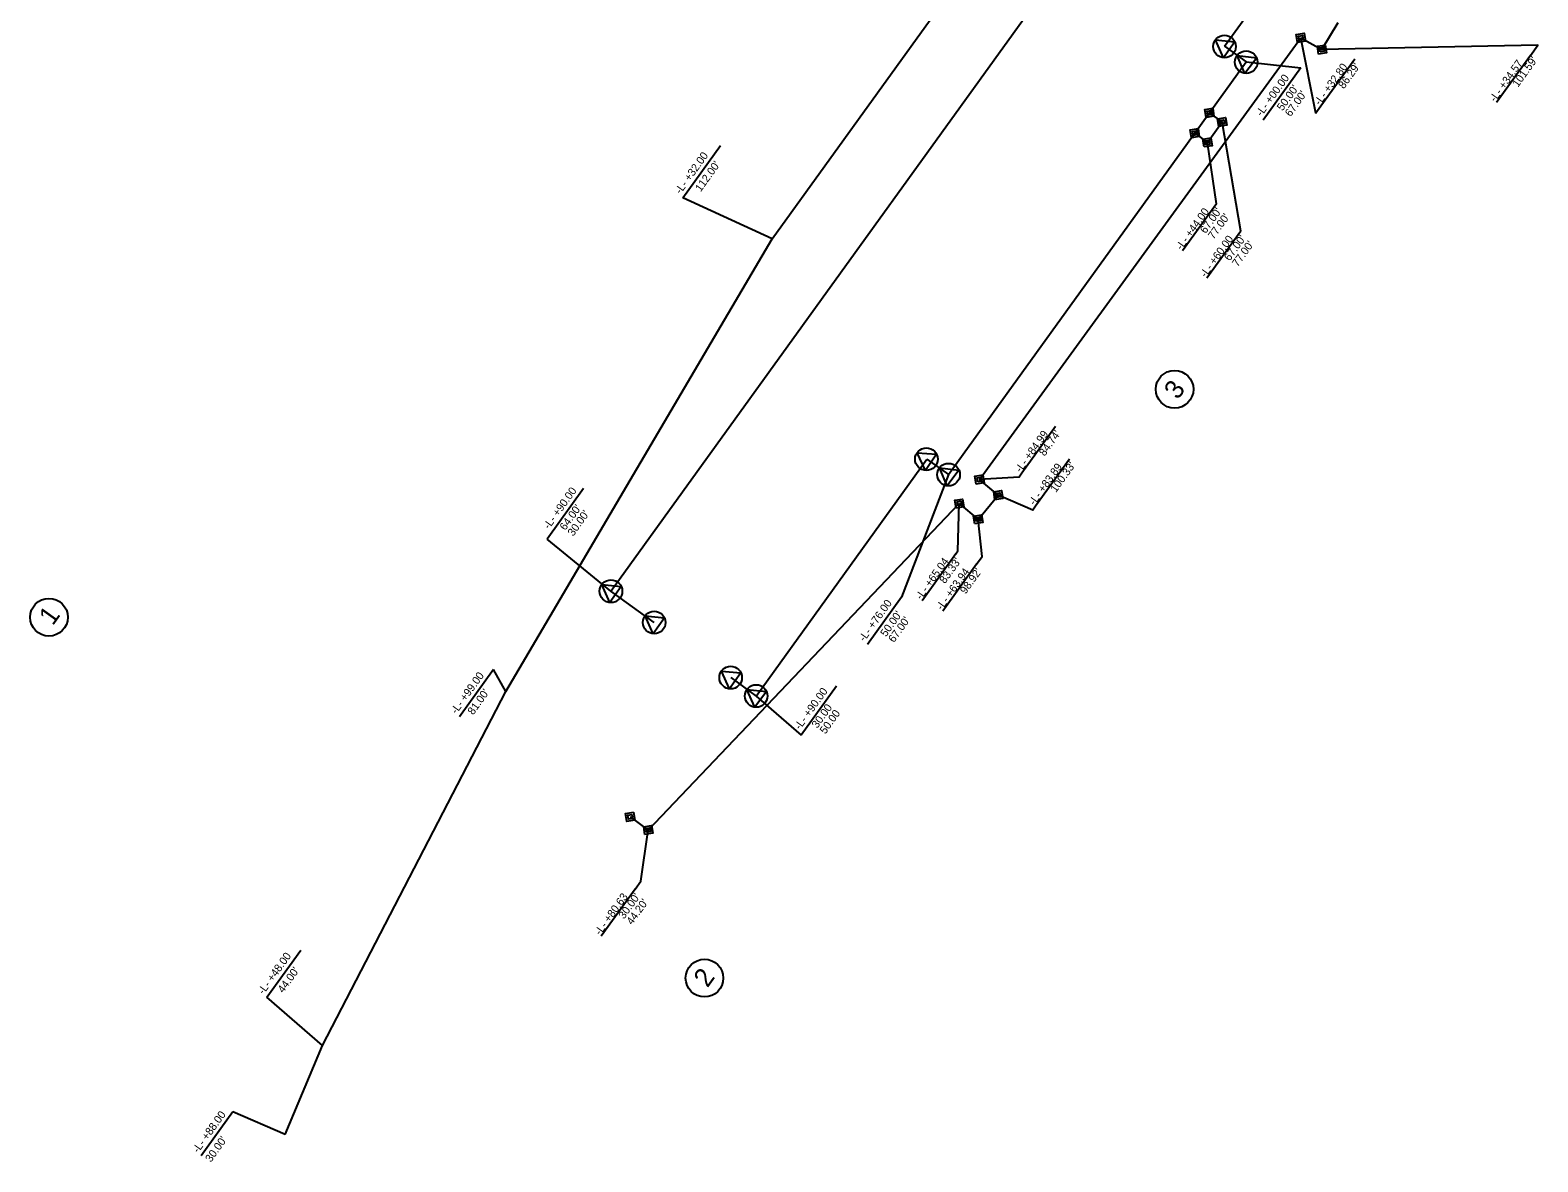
# Model space of a CAD drawing. Extents: x 2189745 to 2190978, y 387331 to 388613.
# Drawn here: x 2189745 to 2190705, y 387331 to 388052 of the extents above; entities that cross this region are included whole.
import ezdxf

# ---------------------------------------------------------------- set-up
doc = ezdxf.new("R2010")
doc.units = 0
for name, color, linetype in [('Prop Easement Construction', 7, 'Continuous'), ('Prop Easement Construction Station Offsets', 7, 'Continuous'), ('Prop Easement Permanent Drainage Utility', 7, 'Continuous'), ('Prop Easement Permanent Drainage Utility Station Offsets', 7, 'Continuous'), ('Prop Easement Permanent Utility', 7, 'Continuous'), ('Prop Easement Permanent Utility Station Offsets', 7, 'Continuous'), ('Prop Parcel Number CELL', 7, 'Continuous'), ('Prop Parcel Number Text', 7, 'Continuous'), ('Prop ROW Marker CELL', 7, 'Continuous'), ('Prop ROW Permanent Easement CELL', 7, 'Continuous'), ('Prop ROW RW Lines', 7, 'Continuous'), ('Prop ROW Station Offsets', 7, 'Continuous')]:
    doc.layers.add(name, color=color, linetype=linetype)

msp = doc.modelspace()

# ---------------------------------------------------------------- linework, layer by layer
at = {"layer": 'Prop Easement Construction'}
for p, q in [((2190048.02, 387630.76), (2190217.66, 387918.98)), ((2189931.21, 387405.53), (2190048.02, 387630.76)), ((2189907.47, 387348.68), (2189931.21, 387405.53))]:
    msp.add_line(p, q, dxfattribs=at)
msp.add_lwpolyline([(2190217.66, 387918.98), (2190318.27, 388058.49), (2190310.97, 388063.75), (2190368.88, 388144.05)], dxfattribs=at)
at = {"layer": 'Prop Easement Construction Station Offsets'}
for p, q in [((2190160.81, 387945.05), (2190184.79, 387978.32)), ((2190217.66, 387918.98), (2190160.81, 387945.05)), ((2190300.07, 387690.79), (2190278.41, 387660.74)), ((2190040.32, 387644.78), (2190018.58, 387614.61)), ((2190048.02, 387630.76), (2190040.32, 387644.78)), ((2189895.79, 387436.15), (2189917.47, 387466.24)), ((2189931.21, 387405.53), (2189895.79, 387436.15)), ((2189874.27, 387363.12), (2189854.11, 387335.14)), ((2189907.47, 387348.68), (2189874.27, 387363.12))]:
    msp.add_line(p, q, dxfattribs=at)
at = {"layer": 'Prop Easement Permanent Drainage Utility'}
msp.add_lwpolyline([(2190486.85, 387986.23), (2190494.96, 387980.38), (2190504.32, 387993.36), (2190496.21, 387999.21)], dxfattribs=at)
at = {"layer": 'Prop Easement Permanent Drainage Utility Station Offsets'}
for p, q in [((2190500.76, 387941.3), (2190494.96, 387980.38)), ((2190500.76, 387941.3), (2190479.15, 387911.34)), ((2190516.13, 387923.84), (2190494.52, 387893.88))]:
    msp.add_line(p, q, dxfattribs=at)
msp.add_lwpolyline([(2190516.13, 387923.84), (2190504.32, 387993.36)], dxfattribs=at)
at = {"layer": 'Prop Easement Permanent Utility'}
for p, q in [((2190567.89, 388039.45), (2190578.21, 388056.67)), ((2190349.73, 387765.77), (2190554.44, 388046.97)), ((2190554.44, 388046.97), (2190567.89, 388039.45)), ((2190361.74, 387755.76), (2190349.73, 387765.77)), ((2190348.92, 387740.4), (2190361.74, 387755.76)), ((2190138.82, 387542.63), (2190336.92, 387750.41)), ((2190336.92, 387750.41), (2190348.92, 387740.4)), ((2190127.35, 387550.93), (2190138.82, 387542.63))]:
    msp.add_line(p, q, dxfattribs=at)
at = {"layer": 'Prop Easement Permanent Utility Station Offsets'}
for p, q in [((2190700.64, 388035.74), (2190679, 388005.74)), ((2190588.88, 388033.41), (2190567.27, 388003.45)), ((2190398.24, 387799.58), (2190376.7, 387769.72)), ((2190407.05, 387778.72), (2190385.52, 387748.86)), ((2190334.76, 387718.44), (2190313.19, 387688.53)), ((2190347.94, 387711.8), (2190326.37, 387681.89)), ((2190130.37, 387504.92), (2190108.89, 387475.14))]:
    msp.add_line(p, q, dxfattribs=at)
for points in [[(2190567.27, 388003.45), (2190564.02, 387998.95), (2190554.44, 388046.97)], [(2190700.64, 388035.74), (2190705.41, 388042.35), (2190567.89, 388039.45)], [(2190376.7, 387769.72), (2190374.95, 387767.28), (2190349.73, 387765.77)], [(2190385.52, 387748.86), (2190383.67, 387746.3), (2190361.74, 387755.76)], [(2190334.76, 387718.44), (2190335.93, 387720.33), (2190336.92, 387750.41)], [(2190347.94, 387711.8), (2190351.5, 387716.75), (2190348.92, 387740.4)], [(2190130.37, 387504.92), (2190134.13, 387510.15), (2190138.82, 387542.63)]]:
    msp.add_lwpolyline(points, dxfattribs=at)
at = {"layer": 'Prop Parcel Number CELL'}
for p, q in [((2190474.06, 387823.18), (2190474.06, 387823.18)), ((2189757.09, 387678.07), (2189757.09, 387678.07)), ((2190174.6, 387448.35), (2190174.6, 387448.35))]:
    msp.add_line(p, q, dxfattribs=at)
for centre in [(2190474.06, 387823.18), (2189757.09, 387678.07), (2190174.6, 387448.35)]:
    msp.add_circle(centre, 12, dxfattribs=at)
at = {"layer": 'Prop ROW Marker CELL'}
for p, q in [((2190505.88, 388041.38), (2190505.88, 388041.38)), ((2190519.68, 388031.44), (2190519.68, 388031.44)), ((2190315.94, 387778.74), (2190315.94, 387778.74)), ((2190330.09, 387768.86), (2190330.09, 387768.86)), ((2190115.04, 387694.62), (2190115.04, 387694.62)), ((2190142.61, 387674.73), (2190142.61, 387674.73)), ((2190191.28, 387639.64), (2190191.28, 387639.64)), ((2190207.5, 387627.94), (2190207.5, 387627.94))]:
    msp.add_line(p, q, dxfattribs=at)
for points in [[(2190505.16, 388034.21), (2190500.03, 388045.58), (2190512.45, 388044.36)], [(2190518.8, 388024.28), (2190513.93, 388035.77), (2190526.32, 388034.27)], [(2190315.34, 387771.55), (2190310.02, 387782.84), (2190322.46, 387781.83)], [(2190329.26, 387761.69), (2190324.3, 387773.14), (2190336.7, 387771.74)], [(2190114.3, 387687.45), (2190109.2, 387698.83), (2190121.61, 387697.59)], [(2190141.88, 387667.56), (2190136.77, 387678.95), (2190149.19, 387677.7)], [(2190190.54, 387632.46), (2190185.44, 387643.85), (2190197.85, 387642.6)], [(2190206.76, 387620.77), (2190201.66, 387632.15), (2190214.08, 387630.9)]]:
    msp.add_lwpolyline(points, close=True, dxfattribs=at)
for centre in [(2190505.88, 388041.38), (2190519.68, 388031.44), (2190315.94, 387778.74), (2190330.09, 387768.86), (2190115.04, 387694.62), (2190142.61, 387674.73), (2190191.28, 387639.64), (2190207.5, 387627.94)]:
    msp.add_circle(centre, 7.2, dxfattribs=at)
at = {"layer": 'Prop ROW Permanent Easement CELL'}
for p, q in [((2190554.44, 388046.97), (2190554.44, 388046.97)), ((2190567.89, 388039.45), (2190567.89, 388039.45)), ((2190496.21, 387999.21), (2190496.21, 387999.21)), ((2190486.85, 387986.23), (2190486.85, 387986.23)), ((2190504.32, 387993.36), (2190504.32, 387993.36)), ((2190494.96, 387980.38), (2190494.96, 387980.38)), ((2190349.73, 387765.77), (2190349.73, 387765.77)), ((2190361.74, 387755.76), (2190361.74, 387755.76)), ((2190336.92, 387750.41), (2190336.92, 387750.41)), ((2190348.92, 387740.4), (2190348.92, 387740.4)), ((2190127.25, 387550.97), (2190127.25, 387550.97)), ((2190138.82, 387542.63), (2190138.82, 387542.63))]:
    msp.add_line(p, q, dxfattribs=at)
for points in [[(2190552.33, 388044.05), (2190551.52, 388049.07), (2190556.54, 388049.89), (2190557.36, 388044.86)], [(2190553.38, 388045.51), (2190552.98, 388048.02), (2190555.49, 388048.43), (2190555.9, 388045.91)], [(2190565.78, 388036.53), (2190564.97, 388041.56), (2190569.99, 388042.37), (2190570.81, 388037.35)], [(2190566.83, 388037.99), (2190566.43, 388040.51), (2190568.94, 388040.91), (2190569.35, 388038.4)], [(2190494.1, 387996.29), (2190493.29, 388001.31), (2190498.31, 388002.12), (2190499.13, 387997.1)], [(2190495.15, 387997.75), (2190494.75, 388000.26), (2190497.26, 388000.67), (2190497.67, 387998.15)], [(2190502.21, 387990.44), (2190501.4, 387995.46), (2190506.42, 387996.28), (2190507.24, 387991.25)], [(2190484.74, 387983.31), (2190483.93, 387988.33), (2190488.95, 387989.15), (2190489.77, 387984.12)], [(2190485.8, 387984.77), (2190485.39, 387987.28), (2190487.9, 387987.69), (2190488.31, 387985.18)], [(2190503.26, 387991.9), (2190502.86, 387994.41), (2190505.37, 387994.82), (2190505.78, 387992.3)], [(2190492.85, 387977.46), (2190492.04, 387982.48), (2190497.06, 387983.3), (2190497.88, 387978.27)], [(2190493.91, 387978.92), (2190493.5, 387981.43), (2190496.01, 387981.84), (2190496.42, 387979.33)], [(2190347.63, 387762.85), (2190346.82, 387767.88), (2190351.84, 387768.69), (2190352.66, 387763.66)], [(2190348.68, 387764.31), (2190348.28, 387766.82), (2190350.79, 387767.23), (2190351.19, 387764.72)], [(2190359.63, 387752.84), (2190358.82, 387757.86), (2190363.84, 387758.68), (2190364.66, 387753.65)], [(2190360.68, 387754.3), (2190360.28, 387756.81), (2190362.79, 387757.22), (2190363.2, 387754.7)], [(2190334.82, 387747.49), (2190334, 387752.52), (2190339.03, 387753.33), (2190339.84, 387748.31)], [(2190335.87, 387748.95), (2190335.46, 387751.47), (2190337.97, 387751.87), (2190338.38, 387749.36)], [(2190346.82, 387737.48), (2190346, 387742.51), (2190351.03, 387743.32), (2190351.84, 387738.29)], [(2190347.87, 387738.94), (2190347.46, 387741.45), (2190349.97, 387741.86), (2190350.38, 387739.35)], [(2190129.35, 387553.89), (2190130.17, 387548.87), (2190125.14, 387548.05), (2190124.33, 387553.08)], [(2190128.3, 387552.43), (2190128.71, 387549.92), (2190126.2, 387549.51), (2190125.79, 387552.03)], [(2190136.71, 387539.71), (2190135.9, 387544.73), (2190140.93, 387545.55), (2190141.74, 387540.52)], [(2190137.77, 387541.17), (2190137.36, 387543.68), (2190139.87, 387544.09), (2190140.28, 387541.58)]]:
    msp.add_lwpolyline(points, close=True, dxfattribs=at)
at = {"layer": 'Prop ROW RW Lines'}
for p, q in [((2190505.82, 388041.59), (2190564.31, 388122.7)), ((2190505.82, 388041.59), (2190519.6, 388031.65)), ((2190330.09, 387768.86), (2190519.6, 388031.65)), ((2190207.5, 387627.94), (2190316.3, 387778.8)), ((2190316.3, 387778.8), (2190330.09, 387768.86)), ((2190191.28, 387639.64), (2190207.5, 387627.94))]:
    msp.add_line(p, q, dxfattribs=at)
msp.add_lwpolyline([(2190142.61, 387674.73), (2190115.04, 387694.62), (2190471.85, 388189.38), (2190499.42, 388169.5)], dxfattribs=at)
at = {"layer": 'Prop ROW Station Offsets'}
for p, q in [((2190519.6, 388031.65), (2190554.44, 388027.75)), ((2190554.44, 388027.75), (2190530.42, 387994.42)), ((2190330.09, 387768.86), (2190300.07, 387690.79)), ((2190097.58, 387760.04), (2190074.37, 387727.82)), ((2190115.04, 387694.62), (2190074.37, 387727.82)), ((2190300.07, 387690.79), (2190278.41, 387660.74)), ((2190258.78, 387634.18), (2190236.29, 387602.97)), ((2190207.5, 387627.94), (2190236.29, 387602.97))]:
    msp.add_line(p, q, dxfattribs=at)

# ---------------------------------------------------------------- texts
at = {"layer": 'Prop Easement Construction Station Offsets'}
for s, p in [('-L- +32.00', (2190159.35, 387947.12)), ("112.00'", (2190172.18, 387948.57)), ('-L- +76.00', (2190276.39, 387662.2)), ('-L- +99.00', (2190016.56, 387616.07)), ("81.00'", (2190027.3, 387615.54)), ('-L- +48.00', (2189893.72, 387437.55)), ("44.00'", (2189906.3, 387438.5)), ('-L- +88.00', (2189852.08, 387336.6)), ("30.00'", (2189860.2, 387330.76))]:
    msp.add_text(s, height=5, rotation=54.22704, dxfattribs=at).set_placement(p)
at = {"layer": 'Prop Easement Permanent Drainage Utility Station Offsets'}
for s, p in [('-L- +44.00', (2190478.45, 387911.48)), ("67.00'", (2190493.78, 387921.96)), ("77.00'", (2190498.89, 387918.28)), ('-L- +60.00', (2190493.82, 387894.02)), ("67.00'", (2190509.14, 387904.5)), ("77.00'", (2190514.26, 387900.81))]:
    msp.add_text(s, height=5, rotation=54.20184, dxfattribs=at).set_placement(p)
at = {"layer": 'Prop Easement Permanent Utility Station Offsets'}
for s, p in [("101.59'", (2190692.74, 388015.13)), ('-L- +32.80', (2190566.57, 388003.59)), ("86.29'", (2190581.89, 388014.07)), ('-L- +34.57', (2190678.19, 388005.73)), ('-L- +84.99', (2190375.98, 387769.82)), ("84.74'", (2190391.26, 387780.24)), ('-L- +83.89', (2190384.79, 387748.97)), ("100.33'", (2190398.46, 387757.14)), ('-L- +65.04', (2190312.61, 387688.84)), ('-L- +63.94', (2190325.79, 387682.21)), ("83.33'", (2190327.78, 387699.1)), ("98.92'", (2190340.95, 387692.46)), ('-L- +80.63', (2190108.19, 387475.28)), ("30.00'", (2190123.38, 387485.58)), ("44.20'", (2190128.5, 387481.89))]:
    msp.add_text(s, height=5, rotation=54.20184, dxfattribs=at).set_placement(p)
at = {"layer": 'Prop Parcel Number Text'}
for s, p in [('3', (2190476.12, 387816.1)), ('1', (2189759.49, 387672.25)), ('2', (2190176.51, 387441.77))]:
    msp.add_text(s, height=12, rotation=54.22704, dxfattribs=at).set_placement(p)
at = {"layer": 'Prop ROW Station Offsets'}
for s, p in [('-L- +00.00', (2190529.42, 387996.55)), ("50.00'", (2190542.78, 388000.07)), ("67.00'", (2190547.89, 387996.38)), ('-L- +90.00', (2190075.54, 387733.73)), ("64.00'", (2190085.92, 387732.99)), ("30.00'", (2190091.04, 387729.3)), ('-L- +76.00', (2190276.39, 387662.2)), ("50.00'", (2190290.19, 387665.24)), ("67.00'", (2190295.3, 387661.56)), ('-L- +90.00', (2190235.44, 387606.07)), ('30.00', (2190246.47, 387607.02)), ('50.00', (2190251.59, 387603.34))]:
    msp.add_text(s, height=5, rotation=54.22704, dxfattribs=at).set_placement(p)

doc.saveas('drawing.dxf')
